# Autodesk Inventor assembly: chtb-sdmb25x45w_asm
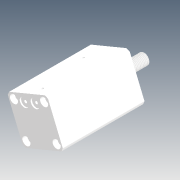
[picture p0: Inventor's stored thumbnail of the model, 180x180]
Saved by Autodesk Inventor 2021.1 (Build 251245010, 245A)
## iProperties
Company: Microsoft
Created: 2018-05
Part Number: chtb-sdmb25x45w_asm
Description: STEP AP214
Document SubType Name: Assembly
Designer: user
Title: chtb-sdmb25x45w_asm.STEP
Author: Windows
Revision Number: ÈÎºÎ
Sending System: SolidWorks 2015
Preprocessor: SwSTEP 2.0
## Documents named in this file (4)
- D:\Vault_2016\Projekty\Clamptek\Hydraulic\CHTB\CHTB-25\Inventor\chtb-sdmb25x45w\chtb-sdmb25x45w_asm.iam
- D:\Vault_2016\Projekty\Clamptek\Hydraulic\CHTB\CHTB-25\Inventor\chtb-sdmb25x45w\CHTB-25QG.ipt
- D:\Vault_2016\Projekty\Clamptek\Hydraulic\CHTB\CHTB-25\Inventor\chtb-sdmb25x45w\CHTB-SDMB25X45NBT.ipt
- D:\Vault_2016\Projekty\Clamptek\Hydraulic\CHTB\CHTB-25\Inventor\chtb-sdmb25x45w\CHTB-SDMB25X45WHSG.ipt
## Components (3 placed, 3 different names)
1. CHTB-25QG_1
2. CHTB-SDMB25X45NBT_2
3. CHTB-SDMB25X45WHSG_3
